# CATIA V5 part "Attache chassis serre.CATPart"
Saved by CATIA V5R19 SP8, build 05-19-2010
Part number: Attache chassis serre
Revision: ANY
Definition: UNKNOWN
Nomenclature: Attache chassis serre
Source: Unknown
Bounding box of the stored display mesh (mm): x -22 to 22, y -33 to 22.5, z 0 to 22.497
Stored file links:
  D:\Documents\1_Travail\1 - ac-limoges.fr\OneDrive - ac-limoges.fr\STI2D_Turgot\2 -2I2D\3_SEQUENCE_Serre_Connectée\3- Spécificités\ITEC\EC 3 Ouverture automatique\Simulation  Ouverture Automatique\Attache chassis serre.CATPart
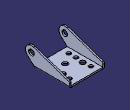
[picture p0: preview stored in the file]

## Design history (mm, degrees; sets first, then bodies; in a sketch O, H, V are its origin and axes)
Body1 "NONE" (main body)
  Solid1: solid without history
Body2 "NONE"
  Solid2: solid without history
Body3 "NONE"
  Solid3: solid without history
